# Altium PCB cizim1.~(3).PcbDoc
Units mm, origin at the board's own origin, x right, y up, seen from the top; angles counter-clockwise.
Board outline 74.6 x 74.6 mm, 2 copper layers (Top Layer, Bottom Layer); 15 components, 13 nets, 60 pads, 0 vias.
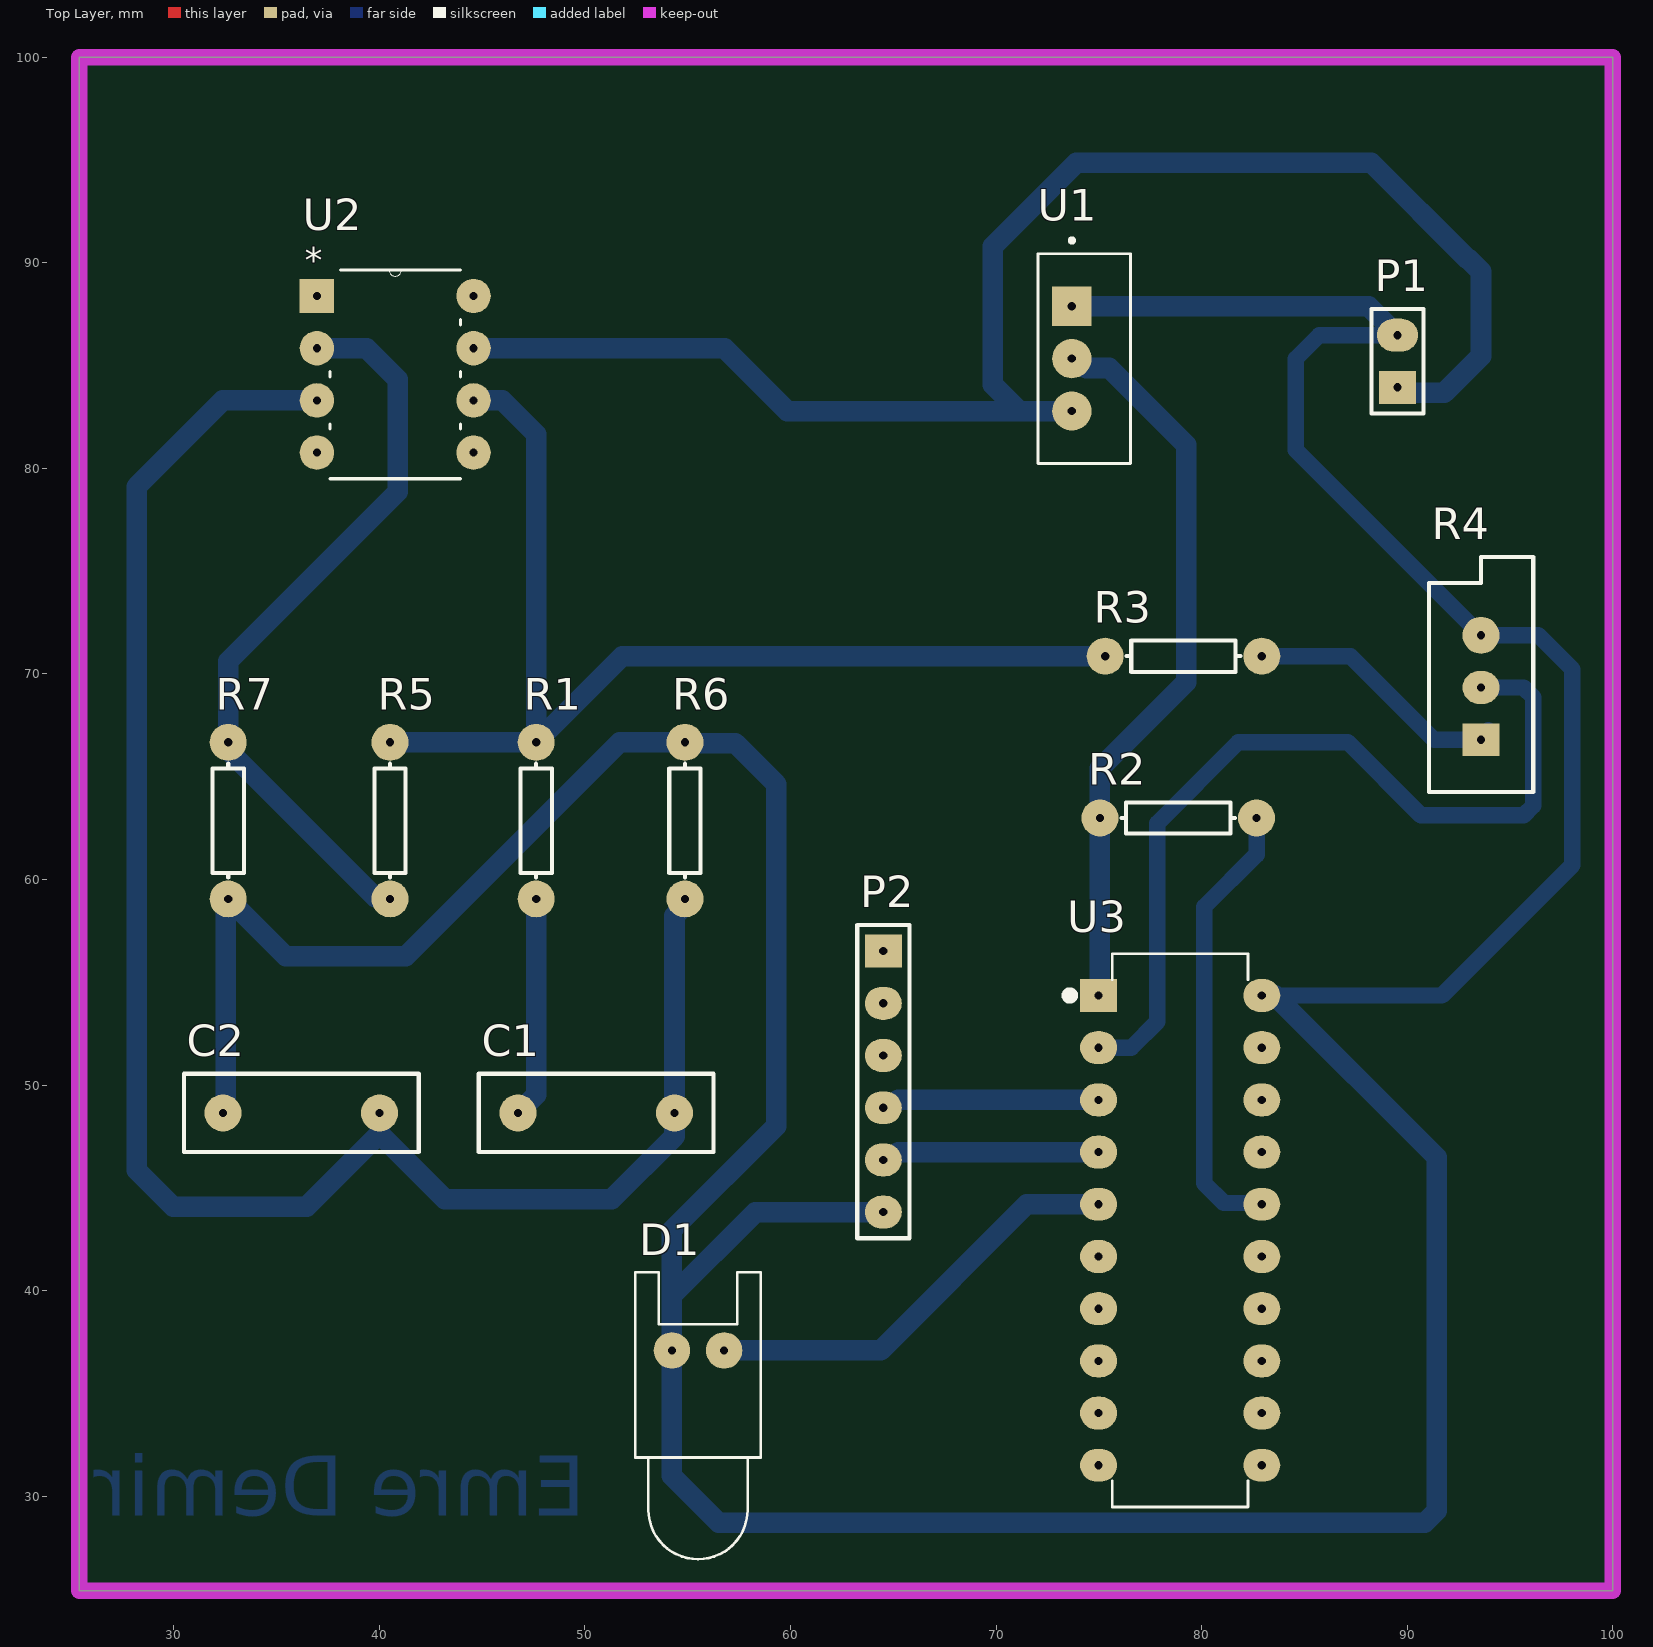
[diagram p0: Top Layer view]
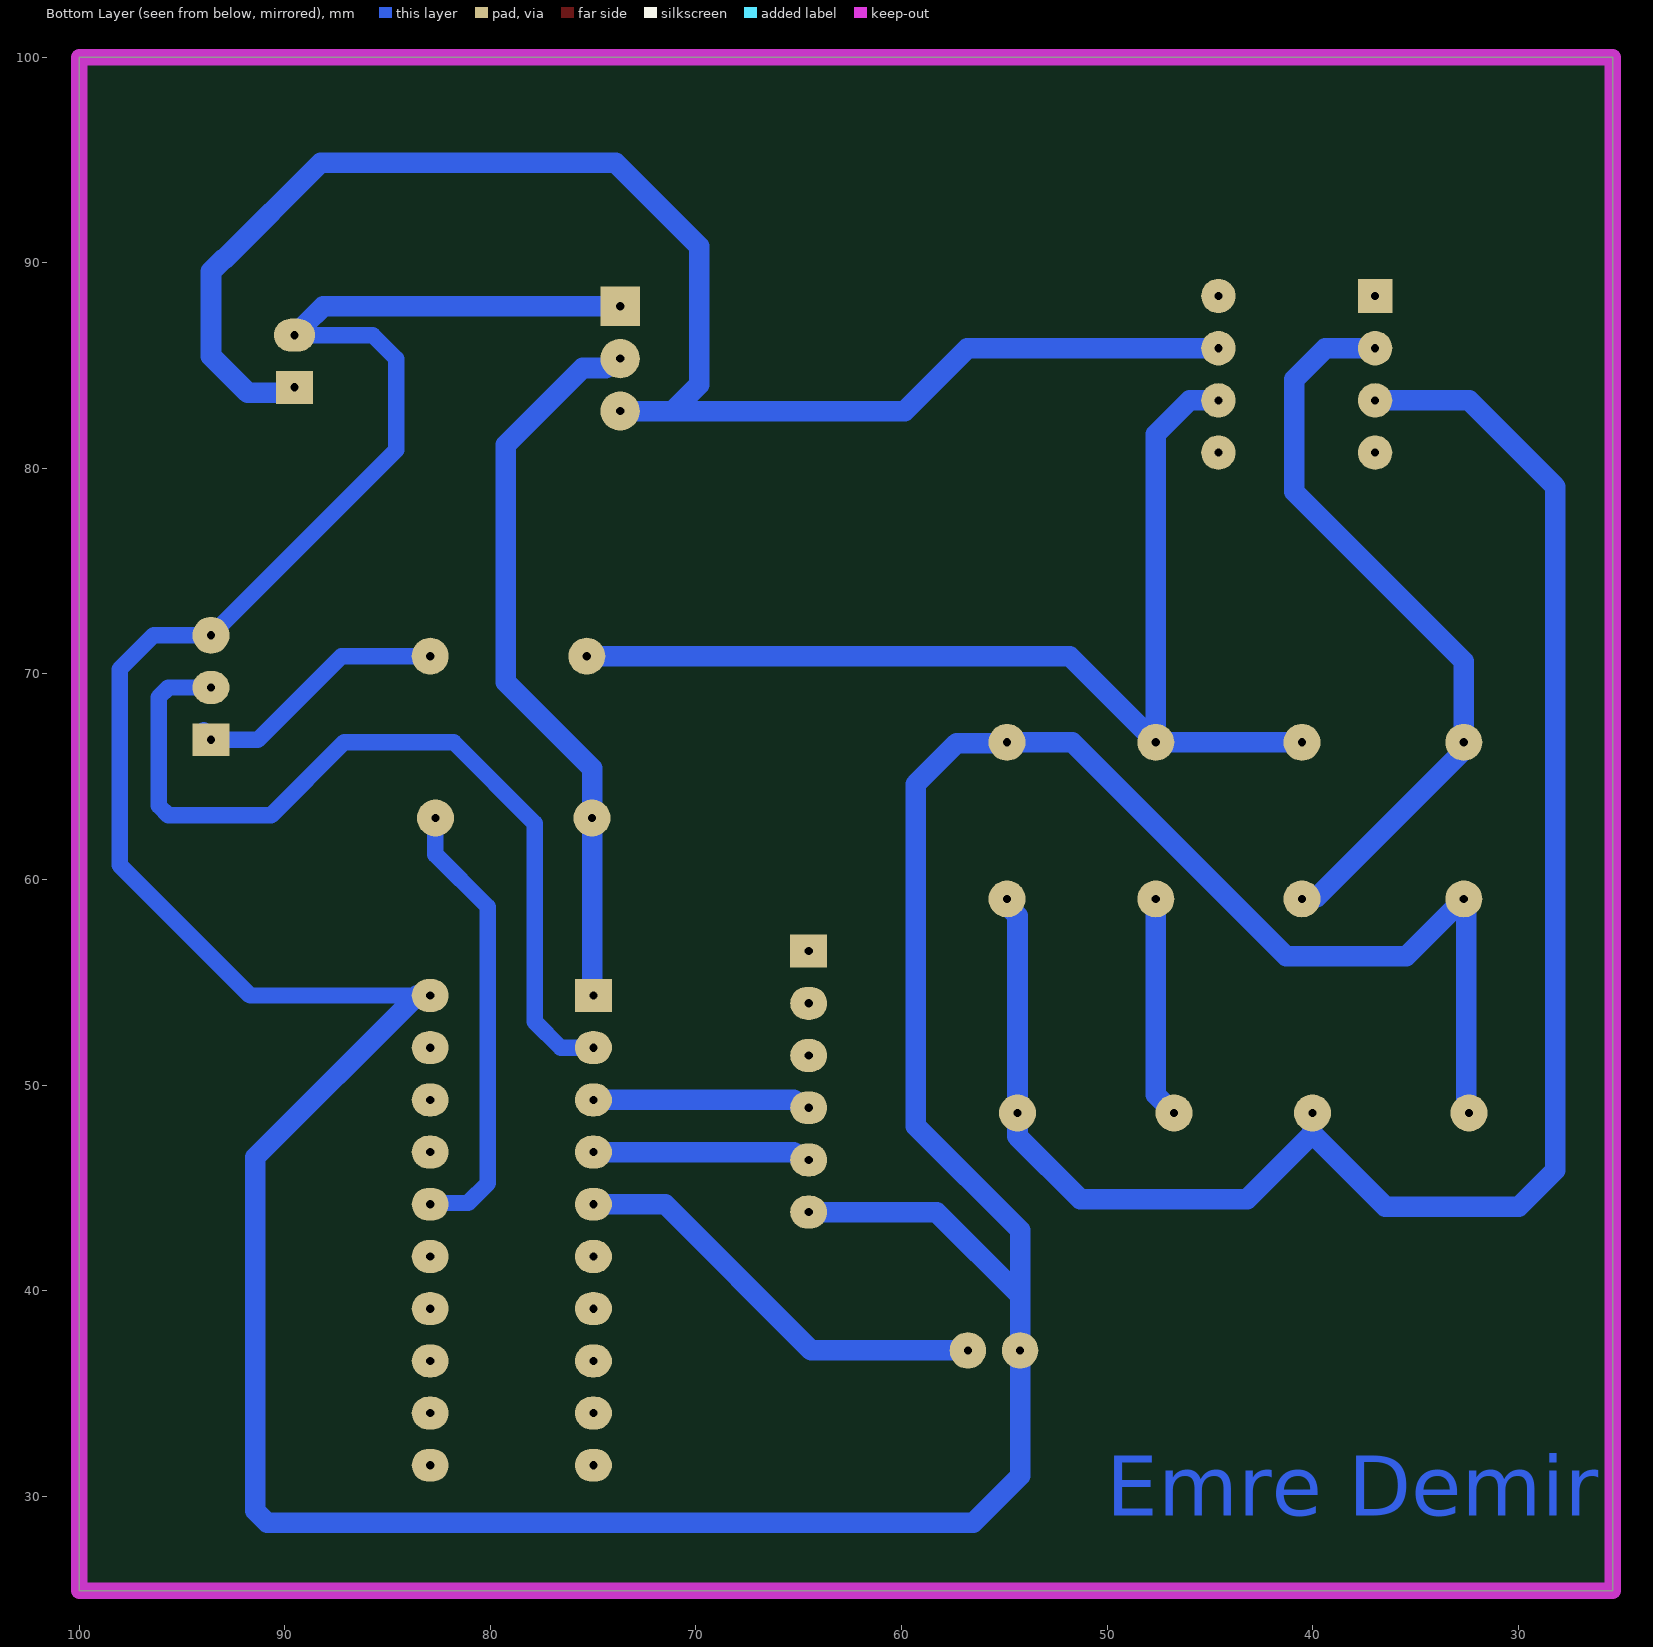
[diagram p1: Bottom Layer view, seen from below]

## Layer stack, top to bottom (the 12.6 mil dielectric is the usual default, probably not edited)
Top Solder: solder mask 0.0102, Solder Resist, Dk 3.5
Top Layer: signal copper 0.0356
Dielectric 1: dielectric 0.32, FR-4, Dk 4.8
Bottom Layer: signal copper 0.0356
Bottom Solder: solder mask 0.0102, Solder Resist, Dk 3.5

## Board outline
25.4,25.4 25.4,100 100,100 100,25.4

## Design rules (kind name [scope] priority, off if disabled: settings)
Clearance [All] p1: gap=0.254 ignorepadtopadclearanceinfootprint=FALSE except(0: Arc-Hole Track-Hole SMDPad-Hole THPad-Hole Via-Hole Fill-Hole Poly-Hole Region-Hole Text-Hole)
PolygonConnect [All] p1: connectstyle=Relief reliefconductorwidth=0.254 reliefentries=4 polygonreliefangle="90 Angle" airgapwidth=0.254
RoutingVias [All] p1: holewidth=0.711 width=1.27 viastyle="Through Hole" minholewidth=0.711 minwidth=1.27 maxholewidth=0.711 maxwidth=1.27
SolderMaskExpansion [All] p1: expansion=0.102 istentingtop=FALSE
Width [All] p1: maxlimit=1.8 minlimit=0.8 preferedwidth=1 bottomlayer_prefwidth=0.8 minimp=50.000000 maximp=50.000000 favimp=50.000000
30 further rules are at their usual default settings.

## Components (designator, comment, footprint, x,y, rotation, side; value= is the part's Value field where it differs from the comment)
C1 "Cap" RAD-0.3 50.546,48.641 r0 top value=1nF
C2 "Cap" RAD-0.3 36.195,48.641 r180 top value=1nF
D1 "LED0" LED-0 55.499,37.084 r0 top
P1 "Header 2" HDR1X2 89.535,83.947 r90 top
P2 "Header 6" HDR1X6 64.516,56.515 r270 top
R1 "Res1" AXIAL-0.3 47.625,62.865 r90 top value=100K
R2 "Res1" AXIAL-0.3 78.867,62.992 r180 top value=47K
R3 "Res1" AXIAL-0.3 79.121,70.866 r180 top value=1K
R4 "RPot" VR5 93.599,69.342 r90 top locked value=1K
R5 "Res1" AXIAL-0.3 40.513,62.865 r270 top value=100K
R6 "Res1" AXIAL-0.3 54.864,62.865 r270 top value=100K
R7 "Res1" AXIAL-0.3 32.639,62.865 r270 top value=47K
U1 "LD1117V33" TO255P1020X450X1968-3 74.295,85.344 r270 top locked
U2 "LM741CN" DIP254P762X508-8 44.577,80.772 r0 top locked
U3 "MSP430G2553IN20" DIP794W45P254L2692H508Q20 78.961,42.926 r0 top locked

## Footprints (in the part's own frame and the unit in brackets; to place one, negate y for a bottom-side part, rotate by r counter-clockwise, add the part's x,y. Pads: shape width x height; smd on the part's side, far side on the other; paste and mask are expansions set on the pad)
AXIAL-0.3 [mm] "Axial Device, Thru-Hole; 2 Leads; 0.3 in Pin Spacing"
  round 1.8 hole 0.4: 1(-3.81,0) 2(3.81,0)
  silkscreen extent -2.77,-0.76 2.77,0.76
DIP254P762X508-8 [mil]
  rect 66x66 hole 15.75: 1(-300,300)
  round 66 hole 15.75: 2(-300,200) 3(-300,100) 4(-300,0) 5(0,0) 6(0,100) 7(0,200) 8(0,300)
  silkscreen extent -275,-50 -25,350, body extent -189,-215 189,215, height 200
DIP794W45P254L2692H508Q20 [mm]
  rect 1.8x1.6 hole 0.4: 1(-3.97,11.43)
  oval 1.8x1.6 hole 0.4: 2(-3.97,8.89) 3(-3.97,6.35) 4(-3.97,3.81) 5(-3.97,1.27) 6(-3.97,-1.27) 7(-3.97,-3.81) 8(-3.97,-6.35) 9(-3.97,-8.89) 10(-3.97,-11.43) 11(3.97,-11.43) 12(3.97,-8.89) 13(3.97,-6.35) 14(3.97,-3.81) 15(3.97,-1.27) 16(3.97,1.27) 17(3.97,3.81) 18(3.97,6.35) 19(3.97,8.89) 20(3.97,11.43)
  silkscreen extent -5.57,-13.46 3.3,13.46
HDR1X2 [mm] "Connector; Header; 2 Position"
  rect 1.6x1.8 hole 0.4: 1(0,0)
  oval 1.6x2 hole 0.4: 2(2.54,0)
  silkscreen extent -1.27,-1.27 3.81,1.27
HDR1X6 [mm] "Connector; Header; 6 Position"
  rect 1.6x1.8 hole 0.4: 1(0,0)
  oval 1.6x1.8 hole 0.4: 2(2.54,0) 3(5.08,0) 4(7.62,0) 5(10.16,0) 6(12.7,0)
  silkscreen extent -1.27,-1.27 13.97,1.27
LED-0 [mil] "LED; 2 Leads"
  round 70 hole 15.75: 1(50,0) 2(-50,0)
  silkscreen extent -120,-400 120,150
RAD-0.3 [mm] "Radial Cap, Thru-Hole; 2 Leads; 0.3 in Pin Spacing"
  round 1.8 hole 0.4: 1(-3.81,0) 2(3.81,0)
  silkscreen extent -5.71,-1.91 5.71,1.91
TO255P1020X450X1968-3 [mm]
  rect 1.91x1.91 / inner round 1.91 / far side rect 1.91x1.91 hole 0.4: 1(-2.55,-0.605)
  round 1.91 hole 0.4: 2(0,-0.605) 3(2.55,-0.605)
  silkscreen extent -5.85,-2.25 5.1,2.25, body extent -4.98,-1.76 4.98,2.69, height 19.68
VR5 [mm] "Thru-Hole; 3 Leads"
  rect 1.6x1.8 hole 0.4: 1(-2.54,0)
  oval 1.6x1.8 hole 0.4: 2(0,0)
  round 1.8 hole 0.4: 3(2.54,0)
  silkscreen extent -5.08,-2.54 6.35,2.54

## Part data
C1 C2: "Capacitor"
D1: "Typical INFRARED GaAs LED"
P1: "Header, 2-Pin"
P2: "Header, 6-Pin"
R1 R2 R3 R5 R6 R7: "Resistor"
R4: "Potentiometer"
U1: "Linear Voltage Regulator IC Positive Fixed 1 Output 800mA TO-220AB", Package="TO-220-3 ON Semiconductor"
U2: "General Purpose Amplifier 1 Circuit 8-DIP", Package="DIP-8 ON Semiconductor"
U3: "MSP430G2x53, MSP430G2x13 Mixed Signal Microcontroller 20-PDIP -40 to 85", Package=None

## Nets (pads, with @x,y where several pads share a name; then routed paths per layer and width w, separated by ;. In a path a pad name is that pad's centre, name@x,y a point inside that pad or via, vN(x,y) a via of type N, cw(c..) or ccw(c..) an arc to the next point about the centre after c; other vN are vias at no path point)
GND: C2.2 D1.2 P1.2 P2.6 R4.3 R6.1 R7.2 U1.1 U3.20 | length 229.4
  Bottom Layer w0.8: U3.20 83.566,54.356 91.694,54.356 98.044,60.706 98.044,70.231 96.393,71.882 R4.3 84.582,80.899 84.582,85.344 85.725,86.487 P1.2
  Bottom Layer w1: C2.2 32.512,48.768 32.512,58.928 R7.2 35.433,56.261 41.275,56.261 51.689,66.675 R6.1 54.907,66.632 57.32,66.632 59.309,64.643 59.309,48.006 54.229,42.926 54.229,39.751 ; P2.6 58.293,43.815 54.229,39.751 ; U1.1 88.128,87.894 89.035,86.987 89.035,86.949 P1.2@89.497,86.487 ; U3.20@83.566,54.356 91.44,46.482 91.44,29.288 90.854,28.702 56.515,28.702 54.229,30.988 D1.2 54.229,39.751
NetC1_1: C1.1 R1.1 | length 10.8
  Bottom Layer w1: C1.1 47.625,49.53 R1.1
NetC1_2: C1.2 C2.1 R6.2 U2.3 | length 87.5
  Bottom Layer w1: U2.3 32.385,83.312 28.194,79.121 28.194,45.847 29.972,44.069 36.449,44.069 40.005,47.625 ; C2.1 40.005,47.625 ; R6.2 54.864,58.745 54.356,58.237 C1.2 54.356,47.498 51.308,44.45 43.18,44.45 40.005,47.625
NetD1_1: D1.1 U3.5 | length 21.2
  Bottom Layer w1: D1.1 64.389,37.084 71.501,44.196 U3.5
NetP1_1: P1.1 U1.3 U2.7 | length 75.6
  Bottom Layer w1: U2.7 56.79,85.852 59.848,82.794 71.13,82.794 ; U1.3 71.13,82.794 ; P1.1 89.789,83.693 91.821,83.693 93.599,85.471 93.599,89.584 93.013,90.17 92.964,90.17 88.265,94.869 73.914,94.869 69.85,90.805 69.85,84.074 71.13,82.794
NetP2_4: P2.4 U3.3 | length 10.6
  Bottom Layer w1: P2.4 64.853,48.895 65.234,49.276 U3.3
NetP2_5: P2.5 U3.4 | length 10.6
  Bottom Layer w1: P2.5 64.853,46.355 65.234,46.736 U3.4
NetR1_2: R1.2 R3.2 R5.1 U2.6 | length 55.3
  Bottom Layer w1: R5.1 R1.2 ; U2.6 45.974,83.312 47.625,81.661 R1.2 ; R3.2 51.816,70.866 R1.2
NetR2_1: R2.1 U3.16 | length 22
  Bottom Layer w0.8: R2.1 82.677,61.214 80.137,58.674 80.137,45.212 81.091,44.258 82.869,44.258 U3.16
NetR2_2: R2.2 U1.2 U3.1 | length 35.9
  Bottom Layer w1: U1.2 73.936,85.344 74.391,84.889 75.512,84.889 79.248,81.153 79.248,69.596 75.057,65.405 R2.2 75.057,54.422 U3.1
NetR3_1: R3.1 R4.1 | length 12.9
  Bottom Layer w0.8: R3.1 87.249,70.866 91.313,66.802 R4.1 93.599,66.902 R4.1@93.949,67.252
NetR4_2: R4.2 U3.2 | length 42.6
  Bottom Layer w0.8: U3.2 76.581,51.816 77.851,53.086 77.851,62.738 81.788,66.675 87.122,66.675 90.678,63.119 95.67,63.119 96.139,63.588 96.139,68.873 95.67,69.342 R4.2
NetR5_2: R5.2 R7.1 U2.2 | length 36.9
  Bottom Layer w1: U2.2 39.37,85.852 40.894,84.328 40.894,78.867 32.639,70.612 R7.1 32.716,66.598 32.716,66.217 39.801,59.132 40.436,59.132 R5.2
pads on no net: P2.1 P2.2 P2.3 U2.1 U2.4 U2.5 U2.8 U3.6 U3.7 U3.8 U3.9 U3.10 U3.11 U3.12 U3.13 U3.14 U3.15 U3.17 U3.18 U3.19

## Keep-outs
Keep-Out Layer:
  the board outline again, w0.8

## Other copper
Bottom Layer:
  text "Emre Demir   200208005" at 50.038,28.067 h5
